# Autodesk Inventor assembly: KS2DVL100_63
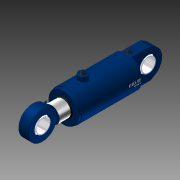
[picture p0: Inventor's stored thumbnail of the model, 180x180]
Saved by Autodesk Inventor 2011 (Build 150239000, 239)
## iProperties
Created: 2010-11
Document SubType Name: Assembly
Designer: TB
Mass: 566.294 g
Surface Area: 1153.75 cm^2
Volume: 566.294 cm^3
Density: 1 g/cm^3
Description: KS2DVL 100/63 - 100 mm
Slaglengde: 100,000 mm
Author: TB
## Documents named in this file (6)
- C:\Vault\Sylinderteknikk\Projects_ST\3D.nettkatalog\KS2-Series\KS2DVL\KS2DVL100_63\KS2DVL100_63.iam
- C:\Vault\Sylinderteknikk\Projects_ST\3D.nettkatalog\KS2-Series\KS2DVL\KS2DVL100_63\KS2DVL100_63_stang.ipt
- C:\Vault\Sylinderteknikk\Projects_ST\3D.nettkatalog\KS2-Series\KS2DVL\KS2DVL100_63\KS2DVL100_63_Parameters.ipt
- C:\Vault\Sylinderteknikk\Projects_ST\3D.nettkatalog\KS2-Series\KS2DVL\KS2DVL100_63\KS2DVL100_63_body..ipt
- C:\Vault\Sylinderteknikk\Projects_ST\Øyer\Klinkby.KS.Øyer\KS.50.eye.Komplett\KS.50.eye.komplett.ipt
- C:\Vault\Sylinderteknikk\Projects_ST\Øyer\Klinkby.KS.Øyer\KS.50.eye.Komplett\Kule50HO.ipt
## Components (5 placed, 5 different names)
1. KS2DVL100_63_Parameters:3
2. KS2DVL100_63_stang:1 — Mate:1, FriMate:2, Mate:3, Insert:1
3. KS2DVL100_63_body.:1 — Mate:1, FriMate:2, Mate:3, Angle:1, Insert:2
4. KS.50.eye.komplett:1 — Insert:1, Angle:1
5. Kule50HO:1 — Insert:2
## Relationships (6: Mate 3, Insert 2, Angle 1)
- Mate:1: KS2DVL100_63_stang:1 ↔ KS2DVL100_63_body.:1
- FriMate:2 [Mate]: KS2DVL100_63_stang:1 ↔ KS2DVL100_63_body.:1
- Mate:3: KS2DVL100_63_stang:1 ↔ KS2DVL100_63_body.:1
- Insert:1: KS2DVL100_63_stang:1 ↔ KS.50.eye.komplett:1
- Angle:1: KS2DVL100_63_body.:1 ↔ KS.50.eye.komplett:1
- Insert:2: KS2DVL100_63_body.:1 ↔ Kule50HO:1
## Named parameters: Forlengelse_rør = 0, Vinkel_Minusport = 0
